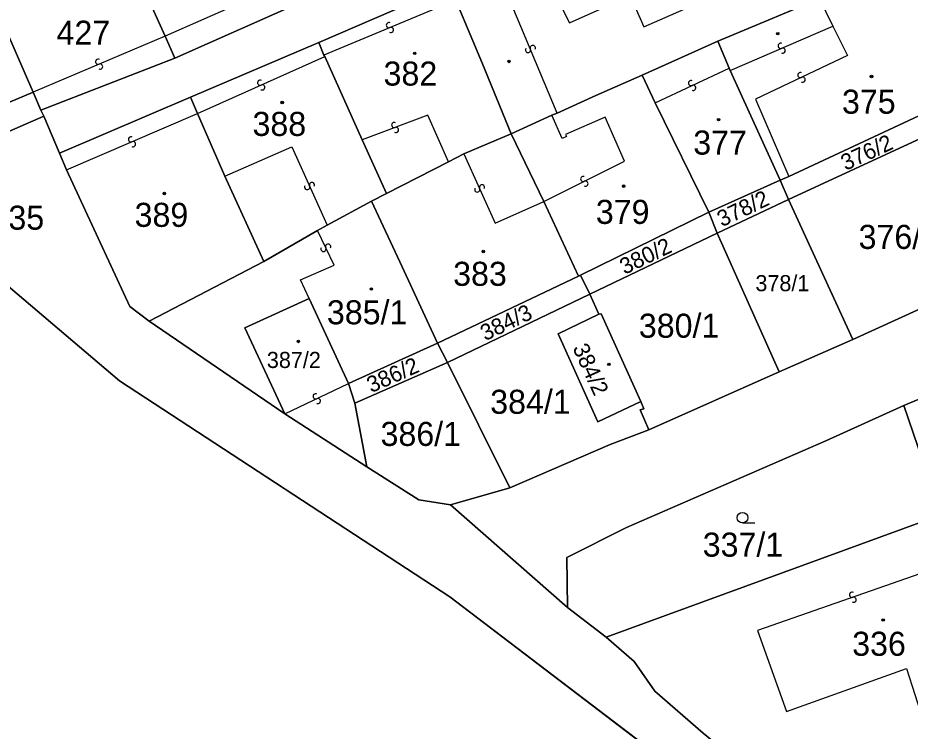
# Model space of a CAD drawing. Extents: x -598233 to -596890, y -1157848 to -1156431.
# Drawn here: x -597333.1 to -597270, y -1157576 to -1157525.6 of the extents above; entities that cross this region are included whole.
import ezdxf

# ---------------------------------------------------------------- set-up
doc = ezdxf.new("R2010")
doc.units = 0
for name, color, linetype in [('Level 1', 7, 'Continuous'), ('Level 13', 7, 'Continuous'), ('Level 3', 7, 'Continuous'), ('Level 4', 7, 'Continuous'), ('Level 5', 7, 'Continuous'), ('Level 60', 7, 'Continuous'), ('Vrstva 54', 7, 'Continuous'), ('Vrstva 60', 7, 'Continuous')]:
    doc.layers.add(name, color=color, linetype=linetype)

msp = doc.modelspace()

# ---------------------------------------------------------------- linework, layer by layer
at = {"layer": 'Level 1'}
for points in [[(-597409.97, -1157511.62), (-597401.88, -1157508.83), (-597373.87, -1157526.16), (-597366.75, -1157525.36), (-597335.98, -1157542.67), (-597325.9, -1157551.23), (-597302.56, -1157566.5), (-597285.2, -1157579.74), (-597270.24, -1157592.06), (-597269.3, -1157592.83), (-597259.47, -1157596.07), (-597250.85, -1157598.17), (-597245.81, -1157601.01), (-597239.94, -1157604.31), (-597223.03, -1157616.87), (-597206.27, -1157628.35), (-597179.87, -1157644.26), (-597115.94, -1157685.24), (-597093.49, -1157698.66), (-597086.96, -1157702.56), (-597050.66, -1157721.6)], [(-597401.88, -1157508.83), (-597373.87, -1157526.16), (-597366.75, -1157525.36), (-597335.98, -1157542.67), (-597325.9, -1157551.23), (-597302.56, -1157566.5), (-597285.2, -1157579.74), (-597270.24, -1157592.06)], [(-597332.01, -1157530.82), (-597336.42, -1157520.74), (-597332.19, -1157518.79)], [(-597324.64, -1157522.53), (-597322.68, -1157526.86)], [(-597311.81, -1157527.32), (-597302.58, -1157523.3)], [(-597312.65, -1157524.26), (-597321.99, -1157528.42)], [(-597298.21, -1157533.78), (-597300.24, -1157528.83), (-597301.98, -1157524.67)], [(-597283.62, -1157527.21), (-597278.19, -1157524.95)], [(-597322.68, -1157526.86), (-597321.99, -1157528.42)], [(-597320.89, -1157531.19), (-597311.81, -1157527.32)], [(-597311.45, -1157528.2), (-597311.81, -1157527.32)], [(-597283.62, -1157527.21), (-597288.96, -1157529.62)], [(-597282.81, -1157529.12), (-597283.62, -1157527.21)], [(-597331.46, -1157532.09), (-597321.99, -1157528.42)], [(-597311.4, -1157528.31), (-597311.45, -1157528.2)], [(-597311.4, -1157528.31), (-597308.74, -1157534.19)], [(-597282.73, -1157529.29), (-597282.81, -1157529.12)], [(-597288.96, -1157529.62), (-597292.24, -1157531.06), (-597294.96, -1157532.3)], [(-597288.96, -1157529.62), (-597288.04, -1157531.57)], [(-597279.2, -1157537.04), (-597282.73, -1157529.29)], [(-597341.18, -1157534.7), (-597332.01, -1157530.82)], [(-597331.46, -1157532.09), (-597332.01, -1157530.82)], [(-597278.6, -1157536.78), (-597265.53, -1157530.69)], [(-597330.14, -1157535.13), (-597320.89, -1157531.19)], [(-597320.38, -1157532.33), (-597320.89, -1157531.19)], [(-597288.04, -1157531.57), (-597284.26, -1157539.32)], [(-597331.25, -1157532.53), (-597331.46, -1157532.09)], [(-597318.46, -1157536.77), (-597320.38, -1157532.33)], [(-597295.34, -1157532.46), (-597294.96, -1157532.3)], [(-597278.62, -1157538.41), (-597264.87, -1157532.05)], [(-597341.18, -1157534.7), (-597340.4, -1157536.5), (-597331.25, -1157532.53)], [(-597331.25, -1157532.53), (-597330.14, -1157535.13)], [(-597298.21, -1157533.78), (-597295.34, -1157532.46)], [(-597308.74, -1157534.19), (-597307.02, -1157537.99)], [(-597298.21, -1157533.78), (-597301.56, -1157535.18)], [(-597298.21, -1157533.78), (-597295.9, -1157538.56)], [(-597329.66, -1157536.32), (-597330.14, -1157535.13)], [(-597301.56, -1157535.18), (-597302.65, -1157535.74)], [(-597302.65, -1157535.74), (-597307.02, -1157537.99)], [(-597323.81, -1157547.02), (-597325.18, -1157545.97), (-597329.66, -1157536.32)], [(-597318.46, -1157536.77), (-597315.7, -1157542.81)], [(-597279.2, -1157537.04), (-597278.6, -1157536.78)], [(-597279.2, -1157537.04), (-597284.26, -1157539.32)], [(-597278.62, -1157538.41), (-597279.2, -1157537.04)], [(-597307.02, -1157537.99), (-597308.09, -1157538.54)], [(-597308.09, -1157538.54), (-597311.22, -1157540.23)], [(-597308.09, -1157538.54), (-597305.93, -1157543.18), (-597303.42, -1157548.58)], [(-597295.9, -1157538.56), (-597293.45, -1157543.83)], [(-597278.62, -1157538.41), (-597283.66, -1157540.79)], [(-597274.06, -1157548.31), (-597278.62, -1157538.41)], [(-597293.31, -1157543.76), (-597284.26, -1157539.32)], [(-597284.26, -1157539.32), (-597283.66, -1157540.79)], [(-597311.91, -1157540.6), (-597315.7, -1157542.81)], [(-597311.22, -1157540.23), (-597311.91, -1157540.6)], [(-597283.66, -1157540.79), (-597292.67, -1157545.12)], [(-597283.66, -1157540.79), (-597279.29, -1157550.61)], [(-597260.14, -1157542.11), (-597262.86, -1157543.19), (-597274.06, -1157548.31)], [(-597315.7, -1157542.81), (-597323.81, -1157547.02)], [(-597293.45, -1157543.83), (-597293.31, -1157543.76)], [(-597292.67, -1157545.12), (-597293.31, -1157543.76)], [(-597303.42, -1157548.58), (-597293.45, -1157543.83)], [(-597314.21, -1157553.58), (-597317.05, -1157547.49), (-597312.49, -1157545.41)], [(-597312.49, -1157545.41), (-597309.71, -1157551.43)], [(-597292.67, -1157545.12), (-597302.73, -1157549.93)], [(-597292.67, -1157545.12), (-597292.02, -1157546.53)], [(-597292.02, -1157546.53), (-597294.9, -1157547.92), (-597292.09, -1157554.13), (-597289.06, -1157552.71)], [(-597292.02, -1157546.53), (-597291.87, -1157546.49), (-597289.06, -1157552.71)], [(-597314.21, -1157553.58), (-597323.81, -1157547.02)], [(-597309.71, -1157551.43), (-597303.42, -1157548.58)], [(-597303.42, -1157548.58), (-597302.73, -1157549.93)], [(-597274.06, -1157548.31), (-597279.29, -1157550.61)], [(-597302.73, -1157549.93), (-597309.26, -1157552.82)], [(-597302.73, -1157549.93), (-597298.31, -1157558.81)], [(-597279.29, -1157550.61), (-597288.49, -1157554.7)], [(-597309.26, -1157552.82), (-597309.71, -1157551.43)], [(-597266.99, -1157551.53), (-597270.46, -1157552.97)], [(-597308.42, -1157557.32), (-597309.26, -1157552.82)], [(-597294.24, -1157567.27), (-597294.28, -1157563.72), (-597290.08, -1157561.61), (-597275.98, -1157555.47), (-597270.46, -1157552.97)], [(-597288.49, -1157554.7), (-597289.1, -1157553.28), (-597288.84, -1157553.21), (-597289.06, -1157552.71)], [(-597267.84, -1157560.72), (-597270.46, -1157552.97)], [(-597314.21, -1157553.58), (-597308.42, -1157557.32)], [(-597298.31, -1157558.81), (-597291.23, -1157555.73), (-597288.49, -1157554.7)], [(-597302.5, -1157560), (-597304.74, -1157559.66), (-597308.42, -1157557.32)], [(-597298.31, -1157558.81), (-597302.5, -1157560)], [(-597294.24, -1157567.27), (-597302.5, -1157560)], [(-597267.84, -1157560.72), (-597291.5, -1157569.36)], [(-597291.5, -1157569.36), (-597294.24, -1157567.27)], [(-597291.5, -1157569.36), (-597289.52, -1157571.08), (-597288.06, -1157573.18), (-597284.65, -1157576.16), (-597280.53, -1157579.54), (-597278.31, -1157581.13), (-597276.13, -1157581.41)]]:
    msp.add_lwpolyline(points, dxfattribs=at)
at = {"layer": 'Level 13'}
for centre, start, end in [((-597306.86, -1157526.09), 59.76068, 292.35068), ((-597306.721, -1157526.431), 239.97514, 112.07313), ((-597297.031, -1157527.84), 150.12718, 22.22518), ((-597296.69, -1157527.7), 329.91273, 202.50273), ((-597279.172, -1157527.55), 60.79034, 292.88833), ((-597279.028, -1157527.889), 240.57588, 113.16588), ((-597327.411, -1157528.67), 60.15646, 292.74646), ((-597327.27, -1157529.01), 240.37091, 112.46891), ((-597277.778, -1157529.613), 62.44398, 295.03398), ((-597277.623, -1157529.947), 242.65844, 114.75644), ((-597315.964, -1157530.151), 61.48896, 293.58695), ((-597315.816, -1157530.488), 241.2745, 113.8645), ((-597285.507, -1157530.182), 62.47353, 294.57153), ((-597285.353, -1157530.517), 242.25908, 114.84908), ((-597306.484, -1157533.147), 57.71432, 290.30432), ((-597306.357, -1157533.493), 237.92878, 110.02678), ((-597325.091, -1157534.16), 60.63835, 292.73635), ((-597324.948, -1157534.499), 240.4239, 113.0139), ((-597293.131, -1157536.964), 64.05849, 296.15649), ((-597312.638, -1157537.535), 151.40748, 23.99748), ((-597312.301, -1157537.386), 331.62194, 203.71994), ((-597300.281, -1157537.555), 331.74617, 203.84417), ((-597292.968, -1157537.295), 243.84404, 116.43404), ((-597300.618, -1157537.705), 151.53171, 24.12171), ((-597311.487, -1157541.908), 153.08972, 25.18771), ((-597311.154, -1157541.751), 332.87526, 205.46526), ((-597312.038, -1157552.333), 62.91017, 295.00816), ((-597311.881, -1157552.666), 242.69571, 115.28571), ((-597274.13, -1157566.366), 56.42942, 289.01942), ((-597274.011, -1157566.715), 236.64387, 108.74187)]:
    msp.add_arc(centre, 0.184, start, end, dxfattribs=at)
at = {"layer": 'Level 3'}
for points in [[(-597282.89, -1157515.77), (-597296.19, -1157521.72), (-597294.09, -1157525.93), (-597289.8, -1157524), (-597288.84, -1157526.21), (-597279.76, -1157522.2)], [(-597313.31, -1157522.72), (-597322.68, -1157526.86)], [(-597294.96, -1157532.3), (-597298.76, -1157523.24), (-597301.98, -1157524.67)], [(-597276.47, -1157524.11), (-597275.48, -1157526.15)], [(-597302.13, -1157524.32), (-597311.45, -1157528.2)], [(-597282.73, -1157529.29), (-597275.48, -1157526.15)], [(-597275.48, -1157526.15), (-597274.44, -1157528.24), (-597280.96, -1157531.32), (-597278.6, -1157536.78)], [(-597322.68, -1157526.86), (-597332.01, -1157530.82)], [(-597320.38, -1157532.33), (-597311.4, -1157528.31)], [(-597288.04, -1157531.57), (-597282.81, -1157529.12)], [(-597329.66, -1157536.32), (-597320.38, -1157532.33)], [(-597302.65, -1157535.74), (-597304.1, -1157532.45), (-597308.74, -1157534.19)], [(-597295.9, -1157538.56), (-597290.21, -1157535.7), (-597291.58, -1157532.6), (-597294.39, -1157533.81), (-597294.32, -1157533.95), (-597294.61, -1157534.11), (-597295.34, -1157532.46)], [(-597318.46, -1157536.77), (-597313.72, -1157534.68), (-597311.22, -1157540.23)], [(-597301.56, -1157535.18), (-597299.34, -1157540.08), (-597295.9, -1157538.56)], [(-597312.49, -1157545.41), (-597313.1, -1157544.09), (-597310.73, -1157543.05), (-597311.91, -1157540.6)], [(-597314.21, -1157553.58), (-597309.71, -1157551.43)], [(-597263.23, -1157577.33), (-597267.32, -1157564.18), (-597280.82, -1157568.9), (-597278.77, -1157574.61), (-597270.28, -1157571.59), (-597267.92, -1157578.94)]]:
    msp.add_lwpolyline(points, dxfattribs=at)
at = {"layer": 'Level 5'}
msp.add_line((-597281.87, -1157561.29), (-597280.995, -1157561.29), dxfattribs=at)
for centre, radius in [((-597279.38, -1157526.69), 0.09), ((-597279.38, -1157526.69), 0.0521), ((-597305.04, -1157528.08), 0.09), ((-597305.04, -1157528.08), 0.0521), ((-597298.37, -1157528.65), 0.09), ((-597298.37, -1157528.65), 0.0521), ((-597272.75, -1157529.72), 0.09), ((-597272.75, -1157529.72), 0.0521), ((-597314.4, -1157531.56), 0.09), ((-597314.4, -1157531.56), 0.0521), ((-597283.56, -1157532.77), 0.09), ((-597283.56, -1157532.77), 0.0521), ((-597290.27, -1157537.47), 0.09), ((-597290.27, -1157537.47), 0.0521), ((-597322.73, -1157537.99), 0.09), ((-597322.73, -1157537.99), 0.0521), ((-597300.19, -1157542.09), 0.09), ((-597300.19, -1157542.09), 0.0521), ((-597308.1, -1157544.74), 0.09), ((-597308.1, -1157544.74), 0.0521), ((-597313.26, -1157548.45), 0.09), ((-597313.26, -1157548.45), 0.0521), ((-597291.31, -1157550.07), 0.09), ((-597291.31, -1157550.07), 0.0521), ((-597281.87, -1157560.915), 0.375), ((-597271.93, -1157568.15), 0.09), ((-597271.93, -1157568.15), 0.0521)]:
    msp.add_circle(centre, radius, dxfattribs=at)
at = {"layer": 'Level 60'}
for points in [[(-597266.55, -1157507.43), (-597275.31, -1157511.29), (-597283.34, -1157514.82), (-597302.58, -1157523.3), (-597311.81, -1157527.32), (-597320.89, -1157531.19), (-597330.14, -1157535.13), (-597331.25, -1157532.53), (-597331.46, -1157532.09), (-597321.99, -1157528.42), (-597312.65, -1157524.26), (-597303.34, -1157520.05), (-597289.94, -1157514.34), (-597287.87, -1157513.17), (-597282.78, -1157510.92), (-597267.76, -1157504.57)], [(-597367.88, -1157576.04), (-597375.32, -1157571.07), (-597383.86, -1157565.29), (-597399.13, -1157555.01), (-597403.51, -1157552.09), (-597406.72, -1157549.47), (-597413.31, -1157544.19), (-597419.51, -1157539.31), (-597416.86, -1157525.08), (-597416.75, -1157524.42), (-597415.01, -1157516.54), (-597414.91, -1157515.95), (-597409.97, -1157511.62), (-597401.88, -1157508.83), (-597373.87, -1157526.16), (-597366.75, -1157525.36), (-597335.98, -1157542.67), (-597325.9, -1157551.23), (-597302.56, -1157566.5), (-597285.2, -1157579.74)], [(-597285.2, -1157579.74), (-597302.56, -1157566.5), (-597325.9, -1157551.23), (-597335.98, -1157542.67), (-597366.75, -1157525.36)], [(-597340.4, -1157536.5), (-597331.25, -1157532.53), (-597330.14, -1157535.13), (-597329.66, -1157536.32), (-597325.18, -1157545.97), (-597323.81, -1157547.02), (-597314.21, -1157553.58), (-597308.42, -1157557.32), (-597304.74, -1157559.66), (-597302.5, -1157560), (-597294.24, -1157567.27), (-597291.5, -1157569.36), (-597289.52, -1157571.08), (-597288.06, -1157573.18), (-597284.65, -1157576.16)], [(-597266.99, -1157551.53), (-597270.46, -1157552.97), (-597275.98, -1157555.47), (-597290.08, -1157561.61), (-597294.28, -1157563.72), (-597294.24, -1157567.27), (-597302.5, -1157560), (-597298.31, -1157558.81), (-597291.23, -1157555.73), (-597288.49, -1157554.7), (-597279.29, -1157550.61), (-597274.06, -1157548.31), (-597262.86, -1157543.19)]]:
    msp.add_lwpolyline(points, dxfattribs=at)
for points in [[(-597341.18, -1157534.7), (-597342.56, -1157531.6), (-597344.33, -1157527.62), (-597344.46, -1157527.31), (-597345.17, -1157525.57), (-597345.58, -1157524.57), (-597344.29, -1157524.1), (-597350.42, -1157510.88), (-597348.1, -1157509.84), (-597344.06, -1157518.73), (-597342.14, -1157519.66), (-597340.17, -1157519.13), (-597337.61, -1157518), (-597330.69, -1157514.99), (-597329.59, -1157517.6), (-597332.19, -1157518.79), (-597336.42, -1157520.74), (-597332.01, -1157530.82)], [(-597324.75, -1157522.28), (-597327.12, -1157516.59), (-597326.53, -1157516.38), (-597324.18, -1157515.57), (-597323.37, -1157515.19), (-597323.48, -1157514.98), (-597321.38, -1157514.01), (-597318.1, -1157512.5), (-597313.31, -1157522.72), (-597312.65, -1157524.26), (-597321.99, -1157528.42), (-597322.68, -1157526.86), (-597324.64, -1157522.53)], [(-597278.19, -1157524.95), (-597283.62, -1157527.21), (-597288.96, -1157529.62), (-597292.24, -1157531.06), (-597294.96, -1157532.3), (-597295.34, -1157532.46), (-597298.21, -1157533.78), (-597300.24, -1157528.83), (-597301.98, -1157524.67), (-597302.13, -1157524.32), (-597302.58, -1157523.3), (-597283.34, -1157514.82), (-597282.89, -1157515.77), (-597280.5, -1157520.36), (-597279.76, -1157522.2), (-597279.06, -1157523.25)], [(-597332.01, -1157530.82), (-597336.42, -1157520.74), (-597332.19, -1157518.79), (-597329.59, -1157517.6), (-597327.12, -1157516.59), (-597324.75, -1157522.28), (-597324.64, -1157522.53), (-597322.68, -1157526.86), (-597321.99, -1157528.42), (-597331.46, -1157532.09)], [(-597267.6, -1157526.11), (-597265.53, -1157530.69), (-597278.6, -1157536.78), (-597279.2, -1157537.04), (-597282.73, -1157529.29), (-597282.81, -1157529.12), (-597283.62, -1157527.21), (-597278.19, -1157524.95), (-597276.47, -1157524.11), (-597274.53, -1157523.25), (-597270.52, -1157521.47), (-597269.91, -1157521.19)], [(-597298.21, -1157533.78), (-597301.56, -1157535.18), (-597302.65, -1157535.74), (-597307.02, -1157537.99), (-597308.74, -1157534.19), (-597311.4, -1157528.31), (-597311.45, -1157528.2), (-597311.81, -1157527.32), (-597302.58, -1157523.3), (-597302.13, -1157524.32), (-597301.98, -1157524.67), (-597300.24, -1157528.83)], [(-597307.02, -1157537.99), (-597308.09, -1157538.54), (-597311.22, -1157540.23), (-597311.91, -1157540.6), (-597315.7, -1157542.81), (-597318.46, -1157536.77), (-597320.38, -1157532.33), (-597320.89, -1157531.19), (-597311.81, -1157527.32), (-597311.45, -1157528.2), (-597311.4, -1157528.31), (-597308.74, -1157534.19)], [(-597282.73, -1157529.29), (-597279.2, -1157537.04), (-597284.26, -1157539.32), (-597288.04, -1157531.57), (-597288.96, -1157529.62), (-597283.62, -1157527.21), (-597282.81, -1157529.12)], [(-597288.96, -1157529.62), (-597288.04, -1157531.57), (-597284.26, -1157539.32), (-597293.31, -1157543.76), (-597293.45, -1157543.83), (-597295.9, -1157538.56), (-597298.21, -1157533.78), (-597295.34, -1157532.46), (-597294.96, -1157532.3), (-597292.24, -1157531.06)], [(-597340.4, -1157536.5), (-597341.18, -1157534.7), (-597332.01, -1157530.82), (-597331.46, -1157532.09), (-597331.25, -1157532.53)], [(-597264.87, -1157532.05), (-597278.62, -1157538.41), (-597279.2, -1157537.04), (-597278.6, -1157536.78), (-597265.53, -1157530.69)], [(-597323.81, -1157547.02), (-597325.18, -1157545.97), (-597329.66, -1157536.32), (-597330.14, -1157535.13), (-597320.89, -1157531.19), (-597320.38, -1157532.33), (-597318.46, -1157536.77), (-597315.7, -1157542.81)], [(-597260.47, -1157541.33), (-597260.14, -1157542.11), (-597262.86, -1157543.19), (-597274.06, -1157548.31), (-597278.62, -1157538.41), (-597264.87, -1157532.05), (-597263.63, -1157534.68), (-597266.75, -1157535.99), (-597266.79, -1157536.34), (-597264.62, -1157540.89), (-597263.22, -1157542.53)], [(-597298.21, -1157533.78), (-597295.9, -1157538.56), (-597293.45, -1157543.83), (-597303.42, -1157548.58), (-597305.93, -1157543.18), (-597308.09, -1157538.54), (-597307.02, -1157537.99), (-597302.65, -1157535.74), (-597301.56, -1157535.18)], [(-597278.62, -1157538.41), (-597283.66, -1157540.79), (-597284.26, -1157539.32), (-597279.2, -1157537.04)], [(-597308.09, -1157538.54), (-597305.93, -1157543.18), (-597303.42, -1157548.58), (-597309.71, -1157551.43), (-597312.49, -1157545.41), (-597317.05, -1157547.49), (-597314.21, -1157553.58), (-597323.81, -1157547.02), (-597315.7, -1157542.81), (-597311.91, -1157540.6), (-597311.22, -1157540.23)], [(-597274.06, -1157548.31), (-597279.29, -1157550.61), (-597283.66, -1157540.79), (-597278.62, -1157538.41)], [(-597293.31, -1157543.76), (-597284.26, -1157539.32), (-597283.66, -1157540.79), (-597292.67, -1157545.12)], [(-597279.29, -1157550.61), (-597288.49, -1157554.7), (-597289.1, -1157553.28), (-597288.84, -1157553.21), (-597289.06, -1157552.71), (-597291.87, -1157546.49), (-597292.02, -1157546.53), (-597292.67, -1157545.12), (-597283.66, -1157540.79)], [(-597293.45, -1157543.83), (-597293.31, -1157543.76), (-597292.67, -1157545.12), (-597302.73, -1157549.93), (-597303.42, -1157548.58)], [(-597308.42, -1157557.32), (-597314.21, -1157553.58), (-597317.05, -1157547.49), (-597312.49, -1157545.41), (-597309.71, -1157551.43), (-597309.26, -1157552.82)], [(-597289.1, -1157553.28), (-597288.49, -1157554.7), (-597291.23, -1157555.73), (-597298.31, -1157558.81), (-597302.73, -1157549.93), (-597292.67, -1157545.12), (-597292.02, -1157546.53), (-597294.9, -1157547.92), (-597292.09, -1157554.13), (-597289.06, -1157552.71), (-597288.84, -1157553.21)], [(-597292.09, -1157554.13), (-597294.9, -1157547.92), (-597292.02, -1157546.53), (-597291.87, -1157546.49), (-597289.06, -1157552.71)], [(-597302.73, -1157549.93), (-597309.26, -1157552.82), (-597309.71, -1157551.43), (-597303.42, -1157548.58)], [(-597302.73, -1157549.93), (-597298.31, -1157558.81), (-597302.5, -1157560), (-597304.74, -1157559.66), (-597308.42, -1157557.32), (-597309.26, -1157552.82)], [(-597262.57, -1157577.22), (-597263.53, -1157574.51), (-597264.11, -1157572.02), (-597266.77, -1157563.87), (-597267.84, -1157560.72), (-597270.46, -1157552.97), (-597266.99, -1157551.53), (-597266.84, -1157553.18), (-597264.73, -1157558.59), (-597263.21, -1157559.36), (-597260.79, -1157558.36), (-597264.06, -1157550.1), (-597262.58, -1157549.47), (-597260.42, -1157554.92), (-597258.04, -1157561.01), (-597255.87, -1157570.07), (-597255.69, -1157570.94), (-597255.21, -1157573.21), (-597254.65, -1157575.87), (-597258.45, -1157576.09)], [(-597270.46, -1157552.97), (-597267.84, -1157560.72), (-597291.5, -1157569.36), (-597294.24, -1157567.27), (-597294.28, -1157563.72), (-597290.08, -1157561.61), (-597275.98, -1157555.47)], [(-597275.29, -1157581.42), (-597276.13, -1157581.41), (-597278.31, -1157581.13), (-597280.53, -1157579.54), (-597284.65, -1157576.16), (-597288.06, -1157573.18), (-597289.52, -1157571.08), (-597291.5, -1157569.36), (-597267.84, -1157560.72), (-597266.77, -1157563.87), (-597264.11, -1157572.02), (-597263.53, -1157574.51), (-597262.57, -1157577.22), (-597263.23, -1157577.33), (-597265.37, -1157578.08), (-597267.92, -1157578.94)]]:
    msp.add_lwpolyline(points, close=True, dxfattribs=at)
at = {"layer": 'Vrstva 54'}
for p, q in [((-597335.98, -1157542.67), (-597325.9, -1157551.23)), ((-597325.9, -1157551.23), (-597302.56, -1157566.5)), ((-597302.56, -1157566.5), (-597285.2, -1157579.74))]:
    msp.add_line(p, q, dxfattribs=at)
at = {"layer": 'Vrstva 60'}
for points in [[(-597285.2, -1157579.74), (-597302.56, -1157566.5), (-597325.9, -1157551.23), (-597335.98, -1157542.67), (-597366.75, -1157525.36), (-597373.87, -1157526.16), (-597401.88, -1157508.83), (-597409.97, -1157511.62), (-597411.67, -1157510.44), (-597417.06, -1157506.7), (-597423.3, -1157502.37), (-597424.47, -1157501.56), (-597426.75, -1157494.36), (-597467.58, -1157472.78), (-597519.06, -1157444.97), (-597538.53, -1157436.14), (-597544.41, -1157433.47), (-597549.68, -1157428.4), (-597584.75, -1157400.18), (-597620.65, -1157379.11), (-597621.47, -1157378.62), (-597672.84, -1157349.01)], [(-597467.58, -1157472.78), (-597426.75, -1157494.36), (-597424.47, -1157501.56), (-597423.3, -1157502.37), (-597417.06, -1157506.7), (-597411.67, -1157510.44), (-597409.97, -1157511.62), (-597401.88, -1157508.83), (-597373.87, -1157526.16), (-597366.75, -1157525.36), (-597335.98, -1157542.67), (-597325.9, -1157551.23), (-597302.56, -1157566.5), (-597285.2, -1157579.74)]]:
    msp.add_lwpolyline(points, dxfattribs=at)

# ---------------------------------------------------------------- texts
at = {"layer": 'Level 4'}
for s, height, p in [('427', 1.7, (-597330.354, -1157527.47)), ('382', 1.7, (-597307.24, -1157530.36)), ('375', 1.7, (-597274.837, -1157532.35)), ('388', 1.7, (-597316.502, -1157533.92)), ('377', 1.7, (-597285.35, -1157535.24)), ('389', 1.7, (-597324.835, -1157540.35)), ('379', 1.7, (-597292.236, -1157540.14)), ('335', 1.7, (-597335.019, -1157540.55)), ('376/1', 1.7, (-597273.663, -1157541.91)), ('383', 1.7, (-597302.321, -1157544.52)), ('378/1', 1.14, (-597280.958, -1157544.9)), ('385/1', 1.7, (-597311.244, -1157547.24)), ('380/1', 1.7, (-597289.196, -1157548.19)), ('387/2', 1.14, (-597315.486, -1157550.33)), ('384/1', 1.7, (-597299.703, -1157553.57)), ('386/1', 1.7, (-597307.453, -1157555.84)), ('337/1', 1.7, (-597284.68, -1157563.67)), ('336', 1.7, (-597274.118, -1157570.68))]:
    msp.add_text(s, height=height, dxfattribs=at).set_placement(p)
for s, rotation, p in [('376/2', 24.82272, (-597274.587, -1157536.398)), ('378/2', 25.27776, (-597283.324, -1157540.379)), ('380/2', 25.66791, (-597290.204, -1157543.749)), ('384/3', 25.55388, (-597300.059, -1157548.442)), ('384/2', 294.34653, (-597293.898, -1157548.91)), ('386/2', 23.87286, (-597308.108, -1157552.112))]:
    msp.add_text(s, height=1.14, rotation=rotation, dxfattribs=at).set_placement(p)

doc.saveas('drawing.dxf')
